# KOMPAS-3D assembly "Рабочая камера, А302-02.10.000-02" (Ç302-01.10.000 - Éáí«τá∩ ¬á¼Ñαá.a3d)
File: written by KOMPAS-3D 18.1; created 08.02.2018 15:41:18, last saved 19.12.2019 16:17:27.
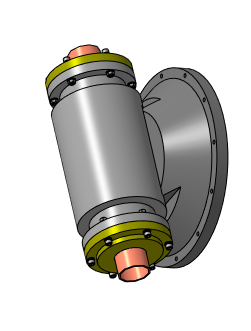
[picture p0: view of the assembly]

Document properties: Автор: Милов; Полное имя файла: D:\Мембранные насосы\Мембранный электропривод\А302-00.00.000 - ASTRA-302 (МЭ200)\3Д ПВХ\А302-01.10.000 - Рабочая камера.a3d

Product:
- Part/product: Рабочая камера  | designation А302-02.10.000-02  | pos. 0
    Масса: 7.91623
    Раздел спецификации: Сборочные единицы
    Форматы листов документа: A3
    source file: А302-01.10.000 - Рабочая камера.cdw
  - Component [assembly]: Крышка рабочей камеры  | designation А302-02.11.000-02  | pos. 1  | Раздел спецификации: Сборочные единицы; Форматы листов документа: A3; source file: А302-01.11.000 - Крышка рабочей камеры.a3d
  - Component [detail]: Седло  | designation А302-01.10.001  | qty 2  | pos. 3  | Материал: Фторопласт-4  ГОСТ 10007-80 Е (density 2200 kg/m3); Масса: 0.0789763; Раздел спецификации: Детали; Форматы листов документа: A4; source file: \\192.168.87.28\Konstructor_doc\Мембранные насосы\Мембранный электропривод\А302-00.00.000 - ASTRA-302 (МЭ200)\3Д ПВХ\А302-01.10.001 - Седло.cdw, А302-01.10.001 - Седло.m3d
  - Component [assembly]: Прижим  | designation А302-01.30.000  | qty 2  | pos. 2  | Материал: Полиамид П-12Б-20  ТУ 6-05-898-73 (density 1020 kg/m3); Масса: 0.266873; Раздел спецификации: Сборочные единицы; Форматы листов документа: A3; source file: А302-01.30.000 - Прижим.a3d, А302-01.30.000 - Прижим.cdw
  - Component [detail]: Штифт 10х40  | qty 4  | pos. 86  | Масса: 0.0246804; Раздел спецификации: Детали; source file: Штифт 10х40.m3d
- Part/product: Рабочая камера  | designation А302-02.10.000-01  | pos. 0
    Масса: 10.6499
    Раздел спецификации: Сборочные единицы
    Форматы листов документа: A3
  - Component [assembly]: Крышка рабочей камеры  | designation А302-02.11.000-01  | pos. 1  | Раздел спецификации: Сборочные единицы; Форматы листов документа: A3; source file: А302-01.11.000 - Крышка рабочей камеры.a3d
  - Component [detail]: Седло  | designation А302-01.10.001  | qty 2  | pos. 3  | Материал: Фторопласт-4  ГОСТ 10007-80 Е (density 2200 kg/m3); Масса: 0.0789763; Раздел спецификации: Детали; Форматы листов документа: A4; source file: \\192.168.87.28\Konstructor_doc\Мембранные насосы\Мембранный электропривод\А302-00.00.000 - ASTRA-302 (МЭ200)\3Д ПВХ\А302-01.10.001 - Седло.cdw, А302-01.10.001 - Седло.m3d
  - Component [assembly]: Прижим  | designation А302-01.30.000  | qty 2  | pos. 2  | Материал: Полиамид П-12Б-20  ТУ 6-05-898-73 (density 1020 kg/m3); Масса: 0.266873; Раздел спецификации: Сборочные единицы; Форматы листов документа: A3; source file: А302-01.30.000 - Прижим.a3d, А302-01.30.000 - Прижим.cdw
- Part/product: Рабочая камера  | designation А302-02.10.000  | pos. 0
    Масса: 6.44594
    Раздел спецификации: Сборочные единицы
    Форматы листов документа: A3
    Комментарий: Версия 2, стаканы внутри корпуса.
  - Component [assembly]: Крышка рабочей камеры  | designation А302-02.11.000  | pos. 1  | Раздел спецификации: Сборочные единицы; Форматы листов документа: A3; source file: А302-01.11.000 - Крышка рабочей камеры.a3d
  - Component [detail]: Седло  | designation А302-01.10.001  | qty 2  | pos. 3  | Материал: Фторопласт-4  ГОСТ 10007-80 Е (density 2200 kg/m3); Масса: 0.0789763; Раздел спецификации: Детали; Форматы листов документа: A4; source file: \\192.168.87.28\Konstructor_doc\Мембранные насосы\Мембранный электропривод\А302-00.00.000 - ASTRA-302 (МЭ200)\3Д ПВХ\А302-01.10.001 - Седло.cdw, А302-01.10.001 - Седло.m3d
  - Component [assembly]: Прижим  | designation А302-01.30.000  | qty 2  | pos. 2  | Материал: Полиамид П-12Б-20  ТУ 6-05-898-73 (density 1020 kg/m3); Масса: 0.266873; Раздел спецификации: Сборочные единицы; Форматы листов документа: A3; source file: А302-01.30.000 - Прижим.a3d, А302-01.30.000 - Прижим.cdw
- Part/product: Рабочая камера  | designation А302-01.10.000  | pos. 0
    Масса: 5.74882
    Раздел спецификации: Сборочные единицы
    Форматы листов документа: A3
    source file: А302-01.10.000 - Рабочая камера.cdw
  - Component [detail]: Гайка шестигранная самостопорящаяся с фланцем / DIN 6927-M6 - A2-70  | qty 6  | pos. 5  | Масса: 0.00415355; Раздел спецификации: Стандартные изделия; Примечание: Нерж., / насечки; source file: ..\..\..\..\2 Стандартные изделия 3D\Гайки\DIN 6927\Гайка шестигранная самостопорящаяся с фланцем DIN 6927-M6 - A2-70.m3d
  - Component [detail]: Гайка шестигранная самостопорящаяся с фланцем / DIN 6927-M6 - A2-70  | qty 6  | pos. 5  | Масса: 0.00415355; Раздел спецификации: Стандартные изделия; source file: ..\..\..\..\2 Стандартные изделия 3D\Гайки\DIN 6927\Гайка шестигранная самостопорящаяся с фланцем DIN 6927-M6 - A2-70.m3d
  - Component [detail]: Кольцо 072-078-25 / материал EPDM ГОСТ 9833-76  | qty 4  | pos. 9  | Материал: Смесь резиновая 3063  ТУ 38-1051082-86 (density 1280 kg/m3); Масса: 0.00150018; Раздел спецификации: Прочие изделия; source file: ..\..\..\..\1 ПКИ 3D\РТИ\Кольца ГОСТ 9833-76\Кольцо 072-78-25 EPDM ГОСТ 9833-76.m3d
  - Component [standard]: Шайба C.6.21 ГОСТ 11371-78  | qty 6  | pos. 8
      Материал: Сталь 12Х18Н10Т ГОСТ 5632-72 (density 1000 kg/m3)
      Масса: 0.00099
      Раздел спецификации: Стандартные изделия
      Примечание: Нерж.
      additional columns: Сталь 12Х18Н10Т ГОСТ 5632-72
      source file: C:\Program Files\ASCON\KOMPAS-3D v18\Libs\PartLib\DATA\VAULT\methods\kompas\3d\PLib_Washer_1_712.m3d
  - Component [standard]: Шайба 6 30Х13 ГОСТ 6402-70  | qty 6  | pos. 7
      Материал: Сталь 30Х13 ГОСТ 5632-72 (density 1000 kg/m3)
      Масса: 0.000376
      Раздел спецификации: Стандартные изделия
      Примечание: Нерж.
      additional columns: Сталь 30Х13 ГОСТ 5632-72
      source file: C:\Program Files\ASCON\KOMPAS-3D v18\Libs\PartLib\DATA\VAULT\methods\kompas\3d\PLib_Washer_2_712.m3d
  - Component [standard]: Винт с цилиндрической головкой и шестигранным углублением под ключ ГОСТ Р ИСО  4762-М6 x 40-A2-70  | qty 6  | pos. 6  | Материал: Нержавеющая сталь (density 1000 kg/m3); Масса: 0.011; Раздел спецификации: Стандартные изделия; additional columns: ГОСТ Р ИСО 4762-2012; М6 x 40 - A2-70; Нержавеющая сталь; source file: C:\Program Files\ASCON\KOMPAS-3D v18\Libs\PartLib\DATA\VAULT\methods\kompas\3d\PLib_Screw_DIN_7984_1500.m3d
  - Component [standard]: Винт с цилиндрической головкой и / шестигранным углублением под ключ / ГОСТ Р ИСО  4762-М6 x 40-A2-70  | qty 6  | pos. 6
      Материал: Нержавеющая сталь (density 1000 kg/m3)
      Масса: 0.011
      Раздел спецификации: Стандартные изделия
      Примечание: Нерж.
      additional columns: Винт с цилиндрической головкой и шестигранным углублением под ключ; ГОСТ Р ИСО 4762-2012; М6 x 40 - A2-70; Нержавеющая сталь
      source file: C:\Program Files\ASCON\KOMPAS-3D v18\Libs\PartLib\DATA\VAULT\methods\kompas\3d\PLib_Screw_DIN_7984_1500.m3d
  - Component [standard]: Шайба 6 30Х13 ГОСТ 6402-70  | qty 6  | pos. 7  | Материал: Сталь 30Х13 ГОСТ 5632-72 (density 1000 kg/m3); Масса: 0.000376; Раздел спецификации: Стандартные изделия; additional columns: Сталь 30Х13 ГОСТ 5632-72; source file: C:\Program Files\ASCON\KOMPAS-3D v18\Libs\PartLib\DATA\VAULT\methods\kompas\3d\PLib_Washer_2_712.m3d
  - Component [standard]: Шайба C.6.21 ГОСТ 11371-78  | qty 6  | pos. 8  | Материал: Сталь 12Х18Н10Т ГОСТ 5632-72 (density 1000 kg/m3); Масса: 0.00099; Раздел спецификации: Стандартные изделия; additional columns: Сталь 12Х18Н10Т ГОСТ 5632-72; source file: C:\Program Files\ASCON\KOMPAS-3D v18\Libs\PartLib\DATA\VAULT\methods\kompas\3d\PLib_Washer_1_712.m3d
  - Component [assembly]: Прижим  | designation А302-01.30.000  | qty 2  | pos. 2  | Материал: Полиамид П-12Б-20  ТУ 6-05-898-73 (density 1020 kg/m3); Масса: 0.266873; Раздел спецификации: Сборочные единицы; Форматы листов документа: A3; source file: \\192.168.87.28\Konstructor_doc\Мембранные насосы\Мембранный электропривод\А302-00.00.000 - ASTRA-302 (МЭ200)\3Д ПВХ\А302-01.30.000 - Прижим.cdw, А302-01.30.000 - Прижим.a3d, А302-01.30.000 - Прижим.cdw
  - Component [detail]: Стакан  | designation А302-01.10.002 3Д  | qty 2  | pos. 4  | Масса: 0.0838758; Раздел спецификации: Детали; Форматы листов документа: -; Примечание: Матрица / АСТРА302-001М; source file: А302-01.10.002 3Д - Стакан.m3d
  - Component [detail]: Седло  | designation А302-01.10.001  | qty 2  | pos. 3  | Материал: Фторопласт-4  ГОСТ 10007-80 Е (density 2200 kg/m3); Масса: 0.0789763; Раздел спецификации: Детали; Форматы листов документа: A4; source file: \\192.168.87.28\Konstructor_doc\Мембранные насосы\Мембранный электропривод\А302-00.00.000 - ASTRA-302 (МЭ200)\3Д ПВХ\А302-01.10.001 - Седло.cdw, А302-01.10.001 - Седло.m3d
  - Component [detail]: Шар @2~60mm PTFE / для мембранного насоса  | qty 2  | pos. 10  | Материал: Фторопласт-4  ГОСТ 10007-80 Е (density 2200 kg/m3); Масса: 0.248814; Раздел спецификации: Прочие изделия; Примечание: Китай; source file: ..\..\..\..\1 ПКИ 3D\2 Китай\Шар PTFE ф60.m3d
  - Component [assembly]: Крышка рабочей камеры  | designation А302-01.11.000  | pos. 1  | Масса: 3.3695; Раздел спецификации: Сборочные единицы; Форматы листов документа: A3; source file: \\192.168.87.28\Konstructor_doc\Мембранные насосы\Мембранный электропривод\А302-00.00.000 - ASTRA-302 (МЭ200)\3Д ПВХ\А302-01.11.000 - Крышка рабочей камеры.cdw, А302-01.11.000 - Крышка рабочей камеры.a3d, А302-01.11.000 - Крышка рабочей камеры.cdw
- Part/product: Рабочая камера  | designation А302-02.10.000-03  | pos. 0
    Материал: Поливинилхлорид (density 1350 kg/m3)
    Масса: 7.54248
    Раздел спецификации: Сборочные единицы
    Форматы листов документа: A3
    source file: А302-02.00.000 - ASTRA-302 (МЭ200)\А302-02.10.000 - Рабочая камера.cdw
  - Component [assembly]: Прижим  | designation А302-01.30.000  | qty 2  | pos. 2  | Материал: Полиамид П-12Б-20  ТУ 6-05-898-73 (density 1020 kg/m3); Масса: 0.266873; Раздел спецификации: Сборочные единицы; Форматы листов документа: A3; source file: А302-01.30.000 - Прижим.a3d, А302-01.30.000 - Прижим.cdw
  - Component [detail]: Седло  | designation А302-01.10.001  | qty 2  | pos. 3  | Материал: Фторопласт-4  ГОСТ 10007-80 Е (density 2200 kg/m3); Масса: 0.0789763; Раздел спецификации: Детали; Форматы листов документа: A4; source file: \\192.168.87.28\Konstructor_doc\Мембранные насосы\Мембранный электропривод\А302-00.00.000 - ASTRA-302 (МЭ200)\3Д ПВХ\А302-01.10.001 - Седло.cdw, А302-01.10.001 - Седло.m3d
  - Component [assembly]: Крышка рабочей камеры  | designation А302-02.11.000  | pos. 1  | Материал: Поливинилхлорид (density 1350 kg/m3); Масса: 5.98117; Раздел спецификации: Сборочные единицы; Форматы листов документа: A3; source file: А302-01.11.000 - Крышка рабочей камеры.a3d, А302-02.00.000 - ASTRA-302 (МЭ200)\А302-02.11.000 - Крышка рабочей камеры.cdw
- Part/product: Рабочая камера  | designation А302-03.10.000  | pos. 0
    Материал: Полипропилен  ГОСТ 26996-86 (density 900 kg/m3)
    Масса: 7.21315
    Раздел спецификации: Сборочные единицы
    Форматы листов документа: A3
    source file: ..\..\А302-03.00.000 - ASTRA-302 (МЭ200)\А302-03.10.000 - Рабочая камера.cdw, ..\Чертежи Полипропилен\А302-03.10.000 - Рабочая камера.cdw
  - Component [assembly]: Крышка рабочей камеры  | designation А302-03.11.000  | pos. 1  | Материал: Поливинилхлорид (density 1350 kg/m3); Масса: 5.69363; Раздел спецификации: Сборочные единицы; Форматы листов документа: A3; source file: ..\..\А302-03.00.000 - ASTRA-302 (МЭ200)\А302-03.11.000 - Крышка рабочей камеры.cdw, ..\Чертежи ПВХ\А302-02.11.000 - Крышка рабочей камеры.cdw, ..\Чертежи Полипропилен\А302-03.11.000 - Крышка рабочей камеры.cdw, А302-01.11.000 - Крышка рабочей камеры.a3d
  - Component [detail]: Седло  | designation А302-01.10.001  | qty 2  | pos. 3  | Материал: Фторопласт-4  ГОСТ 10007-80 Е (density 2200 kg/m3); Масса: 0.0789763; Раздел спецификации: Детали; Форматы листов документа: A4; source file: \\192.168.87.28\Konstructor_doc\Мембранные насосы\Мембранный электропривод\А302-00.00.000 - ASTRA-302 (МЭ200)\3Д ПВХ\А302-01.10.001 - Седло.cdw, А302-01.10.001 - Седло.m3d
  - Component [assembly]: Прижим  | designation А302-03.30.000  | qty 2  | pos. 2  | Материал: Полиамид П-12Б-20  ТУ 6-05-898-73 (density 1020 kg/m3); Масса: 0.245979; Раздел спецификации: Сборочные единицы; Форматы листов документа: A3; source file: ..\Чертежи Полипропилен\А302-03.30.000 - Прижим.cdw, А302-01.30.000 - Прижим.a3d

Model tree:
1. Массив по образцу:1  (6 pattern instances)
2. Массив по образцу:2  (6 pattern instances)
3. Сечение поверхностью:1  (with: Операция вращения:1, Операция выдавливания:9, Отверстие:1, Вырезать элемент выдавливания:2, Операция без истории:1, Вырезать элемент выдавливания:1)  (labels: Операция выдавливания:1; Операция выдавливания:1; Операция выдавливания:1; Операция выдавливания:1)
     Расстояние = -2; Расстояние = 2; Расстояние = -16.7; Расстояние = 6.2; Расстояние = 17; Расстояние = 6.3

Expressions: A2-70
Referenced files in D:\Мембранные насосы\Мембранный электропривод\А302-00.00.000 - ASTRA-302 (МЭ200)\3Д ПВХ\: А302-01.11.000 - Крышка рабочей камеры.a3d, А302-01.11.000 - Крышка рабочей камеры.cdw, А302-01.10.001 - Седло.m3d, А302-01.10.001 - Седло.cdw, А302-01.10.002 3Д - Стакан.m3d, А302-01.30.000 - Прижим.a3d, А302-01.30.000 - Прижим.cdw, Штифт 10х40.m3d, А302-01.10.000 - Рабочая камера.cdw
Referenced files in D:\1 ПКИ 3D\2 Китай\: Шар PTFE ф60.m3d
Referenced files in C:\Program Files\ASCON\KOMPAS-3D v18\Libs\PartLib\DATA\VAULT\methods\kompas\3d\: PLib_Washer_1_712.m3d, PLib_Washer_2_712.m3d, PLib_Screw_DIN_7984_1500.m3d
Referenced files in D:\2 Стандартные изделия 3D\Гайки\DIN 6927\: Гайка шестигранная самостопорящаяся с фланцем DIN 6927-M6 - A2-70.m3d
Referenced files in D:\1 ПКИ 3D\РТИ\Кольца ГОСТ 9833-76\: Кольцо 072-78-25 EPDM ГОСТ 9833-76.m3d
Referenced files in \\192.168.87.28\Konstructor_doc\1 ПКИ 3D\РТИ\Кольца ГОСТ 9833-76\: Кольцо 072-78-25 EPDM ГОСТ 9833-76.m3d
Referenced files in \\192.168.87.28\Konstructor_doc\Мембранные насосы\Мембранный электропривод\А302-00.00.000 - ASTRA-302 (МЭ200)\3Д ПВХ\: А302-01.10.001 - Седло.cdw
Referenced files in D:\Мембранные насосы\Мембранный электропривод\А302-00.00.000 - ASTRA-302 (МЭ200)\3Д ПВХ\А302-02.00.000 - ASTRA-302 (МЭ200)\: А302-02.11.000 - Крышка рабочей камеры.cdw
Referenced files in D:\Мембранные насосы\Мембранный электропривод\А302-00.00.000 - ASTRA-302 (МЭ200)\Чертежи Полипропилен\: А302-03.30.000 - Прижим.cdw, А302-03.11.000 - Крышка рабочей камеры.cdw
Referenced files in D:\Мембранные насосы\Мембранный электропривод\А302-03.00.000 - ASTRA-302 (МЭ200)\: А302-03.11.000 - Крышка рабочей камеры.cdw
Referenced files in D:\Мембранные насосы\Мембранный электропривод\А302-00.00.000 - ASTRA-302 (МЭ200)\Чертежи ПВХ\: А302-02.11.000 - Крышка рабочей камеры.cdw
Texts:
  для мембранного насоса
  АСТРА302-001М
  Матрица / АСТРА302-001М
  Крепежное изделие ГОСТ
  Гайка шестигранная самостопорящаяся с фланцем
  DIN 6927-M6 - A2-70
  Нерж., / насечки
  Винт с цилиндрической головкой и
  шестигранным углублением под ключ
  ГОСТ Р ИСО  4762-М6 x 40-A2-70
  Винт с цилиндрической головкой и шестигранным углублением под ключ
  Кольцо 072-078-25
  материал EPDM ГОСТ 9833-76
  Винт с цилиндрической головкой и шестигранным углублением под ключГОСТ Р ИСО 4762-М6x40-A2-70
  Точка начала. Х
  Точка начала. Y
  Точка начала. Z
  Штифт 10х40 (1)
  Штифт 10х40 (2)
  Штифт 10х40 (3)
  Штифт 10х40 (4)
  Hexagon socket for cylindrical head

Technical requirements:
  Gost Type A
